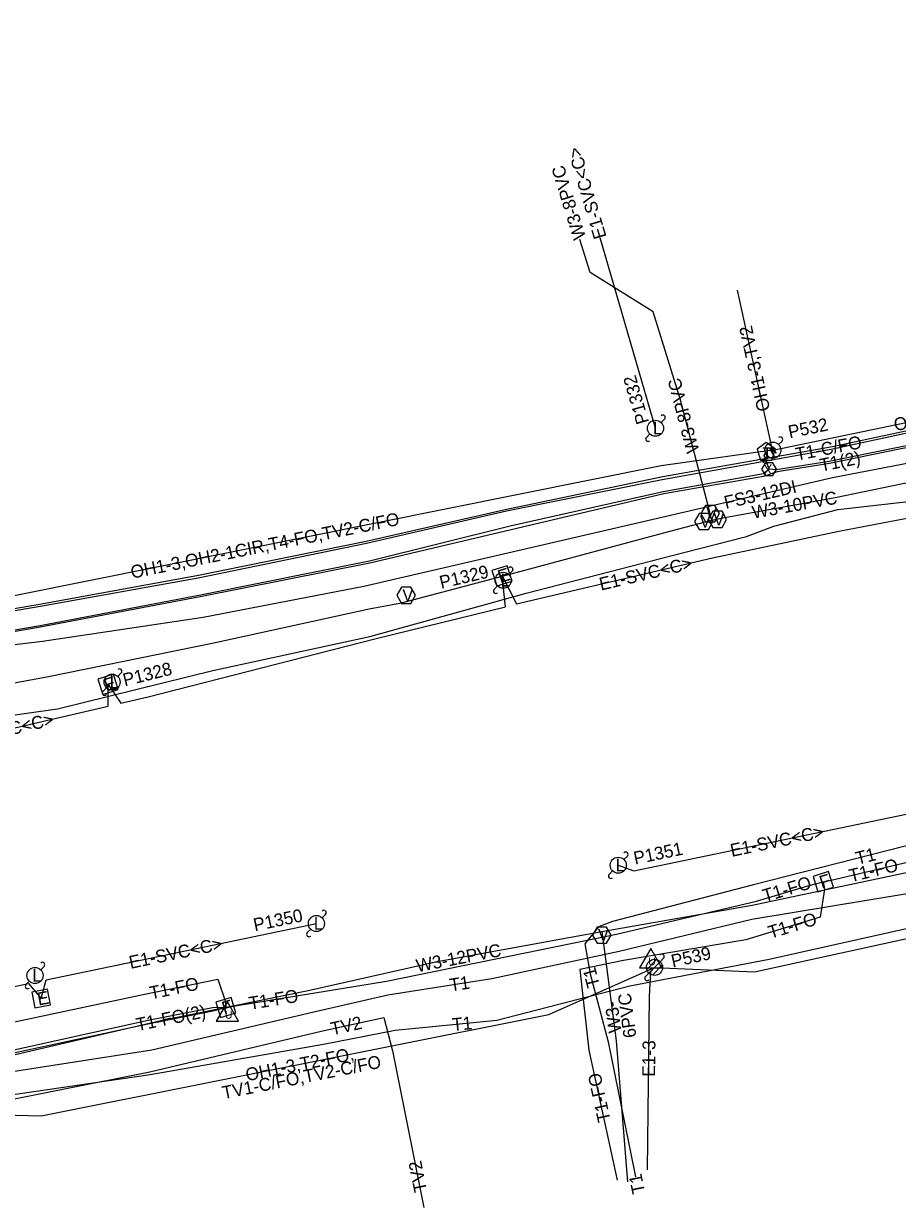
# Model space of a CAD drawing. Extents: x 2336688 to 2352634, y 362473 to 369571.
# Drawn here: x 2347488.6 to 2347760, y 367293.4 to 367661.1 of the extents above; entities that cross this region are included whole.
import ezdxf

# ---------------------------------------------------------------- set-up
doc = ezdxf.new("R2010")
doc.units = 0
for name, color, linetype in [('RD_EX_DV_Prop', 7, 'Continuous'), ('RD_EX_DV_TX_Prop', 7, 'Continuous'), ('RD_EX_RW', 7, 'Continuous'), ('RD_EX_RW_TX', 7, 'Continuous'), ('RD_HC_Data_Tic', 7, 'Continuous'), ('RD_PD_CstnLmt', 7, 'Continuous'), ('RD_PD_Final_TrvlWay', 7, 'Continuous'), ('RD_PD_PatLn3', 7, 'Continuous'), ('RD_PD_PatLn4', 7, 'Continuous'), ('RD_SHT_ShtClip', 7, 'Continuous'), ('RD_Sketch1', 7, 'Continuous'), ('RD_Sketch2', 7, 'Continuous'), ('RD_Sketch5', 7, 'Continuous')]:
    doc.layers.add(name, color=color, linetype=linetype)

msp = doc.modelspace()

# ---------------------------------------------------------------- linework, layer by layer
at = {"layer": 'RD_EX_RW_TX'}
for points in [[(2347470.44, 367444.23), (2347499.15, 367448.23), (2347547.38, 367460.16), (2347596.2, 367470.73), (2347644.67, 367484.24), (2347693.24, 367496.74), (2347713.15, 367501.75), (2347721.65, 367505), (2347741.52, 367510.17), (2347791.62, 367515.85), (2347841.03, 367525.03), (2347889.66, 367537.7), (2347924.48, 367550.59), (2347930.04, 367554.24), (2347932.17, 367555.74), (2347934, 367561.09), (2347931.82, 367574.4), (2347929.65, 367586.41), (2347915.95, 367650.55), (2347902.14, 367697.01)], [(2348277.67, 367644.22), (2348273.84, 367645.8), (2348227.29, 367635.33), (2348178.6, 367623.03), (2348133.33, 367611.87), (2348080.21, 367600.2), (2348034.92, 367588.57), (2348009.29, 367585.15), (2347982.98, 367580.09), (2347935.21, 367568.08), (2347896.24, 367563.27), (2347883.18, 367561.78), (2347837.9, 367550.42), (2347785.45, 367539.42), (2347739.83, 367529.65), (2347687.13, 367520.3), (2347638.22, 367510.11), (2347594.98, 367500.2), (2347542.99, 367489.7), (2347493.07, 367480.59), (2347455.62, 367474.3)], [(2348273.75, 367646.44), (2348227.32, 367635.79), (2348178.43, 367623.86), (2348133.17, 367612.62), (2348080.1, 367600.69), (2348034.75, 367588.91), (2347982.83, 367580.63), (2347949.32, 367569.72), (2347947.83, 367569.22), (2347941.99, 367566.16), (2347925.16, 367563.38), (2347893.98, 367560.65), (2347889.37, 367561.99), (2347883.21, 367561.02), (2347838.01, 367549.55), (2347785.59, 367538.72), (2347739.47, 367528.78), (2347686.93, 367519.36), (2347638.55, 367509.72), (2347595.16, 367499.67), (2347542.86, 367488.84), (2347493.21, 367479.93), (2347455.71, 367473.66)], [(2348277.67, 367644.22), (2348273.99, 367643.66), (2348228.58, 367631.8), (2348180.44, 367618.2), (2348135.72, 367603.5), (2348082.46, 367593.52), (2348035.48, 367584.74), (2347984.84, 367574.01), (2347951.44, 367567.02), (2347939.95, 367565.03), (2347935.77, 367564.67), (2347885.73, 367554.51), (2347837.63, 367544.73), (2347786.79, 367534.85), (2347738.82, 367525.14), (2347722.47, 367522.46), (2347720.16, 367522.7), (2347718.41, 367521.27), (2347687.23, 367515.7), (2347639.77, 367505.05), (2347596.04, 367494.09), (2347543.53, 367483.61), (2347493.77, 367474.07), (2347444.64, 367465.68)], [(2348277.67, 367644.22), (2348274.19, 367643.16), (2348263.65, 367639.56), (2348260.75, 367638.41), (2348228.6, 367631.4), (2348180.48, 367617.57), (2348135.89, 367603.05), (2348082.6, 367592.95), (2348035.55, 367584.09), (2347984.98, 367573.4), (2347951.16, 367566.33), (2347935.9, 367564.13), (2347885.75, 367553.87), (2347837.61, 367543.77), (2347786.94, 367534.28), (2347738.95, 367524.48), (2347722.65, 367521.86), (2347718.4, 367520.47), (2347687.46, 367515.07), (2347596.2, 367493.52), (2347543.48, 367483.07), (2347493.75, 367473.66), (2347444.81, 367465.06)], [(2347720.16, 367522.7), (2347718.58, 367527), (2347719.26, 367527.98)], [(2347470.17, 367338.02), (2347527.74, 367350.46), (2347547.36, 367354.41), (2347551.42, 367355.46), (2347554.94, 367356.11), (2347601.32, 367363.67), (2347672.79, 367378.26), (2347716.22, 367388.49), (2347732.21, 367393.25), (2347737, 367394.55), (2347740.32, 367395.23), (2347763.96, 367400.82), (2347812.85, 367411.94), (2347861.88, 367418.78), (2347886.02, 367419.64), (2347912.08, 367422.89), (2347964.53, 367437), (2348014.8, 367447.66), (2348042.92, 367455.01), (2348073.57, 367461.89), (2348119.92, 367473.29), (2348155.43, 367480.43), (2348206.38, 367490.17), (2348251.79, 367501.21)], [(2347762.8, 367405.7), (2347714.95, 367393.51), (2347671.52, 367382.16), (2347667.2, 367380.52), (2347662.95, 367375.22), (2347664.63, 367365.92), (2347670.14, 367344.81), (2347678.66, 367302.9)], [(2347737, 367394.55), (2347737.39, 367392.18), (2347736.03, 367383.58), (2347712.91, 367376.53), (2347674.98, 367370.11), (2347661.36, 367367.28), (2347664.2, 367342.23), (2347672.96, 367301.87)], [(2347471.76, 367333.48), (2347528.47, 367342.27), (2347578.72, 367354.1), (2347601.79, 367359.4), (2347634.08, 367364.43), (2347673.56, 367372.98), (2347714.77, 367382.86), (2347763.63, 367391.02)], [(2347473.23, 367326.64), (2347527.97, 367334.66), (2347581.75, 367344.07), (2347604.03, 367348.39), (2347635.63, 367351.49), (2347676.92, 367362.19), (2347720.23, 367370.45), (2347766.06, 367380.72)], [(2347468.18, 367347.3), (2347525.21, 367359.4), (2347548.99, 367364.25), (2347551.29, 367357.19), (2347551.42, 367355.46)], [(2347551.42, 367355.46), (2347547.27, 367355.37), (2347527.34, 367351.4), (2347470.01, 367338.79)], [(2347455.53, 367322.31), (2347459.94, 367322.89), (2347473.65, 367324.69), (2347527.79, 367335.44), (2347581.01, 367348.1), (2347600.51, 367352.4), (2347603.18, 367342.01), (2347612.97, 367293.38)]]:
    msp.add_lwpolyline(points, dxfattribs=at)
for points in [[(2347719.26, 367530.98), (2347716.41, 367528.91), (2347717.5, 367525.56), (2347721.02, 367525.56), (2347722.11, 367528.91)], [(2347717.85, 367522.7), (2347719.01, 367520.7), (2347721.32, 367520.7), (2347722.47, 367522.7), (2347721.32, 367524.7), (2347719.01, 367524.7)], [(2347738.66, 367397.67), (2347733.88, 367396.21), (2347735.34, 367391.43), (2347740.12, 367392.89)], [(2347553.08, 367358.58), (2347548.3, 367357.13), (2347549.76, 367352.34), (2347554.54, 367353.8)]]:
    msp.add_lwpolyline(points, close=True, dxfattribs=at)
at = {"layer": 'RD_HC_Data_Tic'}
for p, q in [((2347686.64, 367537.19), (2347687.7, 367538.25)), ((2347682.04, 367532.6), (2347683.1, 367533.66)), ((2347724.17, 367531.46), (2347723.1, 367530.4)), ((2347719.57, 367526.87), (2347718.51, 367525.81)), ((2347639.34, 367489.97), (2347640.4, 367491.03)), ((2347634.74, 367485.37), (2347635.8, 367486.43)), ((2347517.88, 367458.33), (2347518.94, 367459.39)), ((2347513.28, 367453.73), (2347514.35, 367454.79)), ((2347675.08, 367401.43), (2347676.14, 367402.49)), ((2347670.48, 367396.83), (2347671.54, 367397.89)), ((2347581.32, 367383.31), (2347582.38, 367384.38)), ((2347576.73, 367378.72), (2347577.79, 367379.78)), ((2347685.21, 367370.34), (2347682.15, 367367.28)), ((2347686.33, 367369.7), (2347682.8, 367366.16)), ((2347687.39, 367370.76), (2347686.33, 367369.7)), ((2347493.93, 367367.17), (2347494.99, 367368.23)), ((2347682.8, 367366.16), (2347681.74, 367365.1)), ((2347686.98, 367368.58), (2347683.92, 367365.51)), ((2347489.34, 367362.57), (2347490.4, 367363.63))]:
    msp.add_line(p, q, dxfattribs=at)
msp.add_lwpolyline([(2347721.73, 367526.62), (2347720.9, 367528.64), (2347722.36, 367527.84), (2347720.49, 367530.52), (2347720.49, 367530.52), (2347721.69, 367528.42), (2347720.31, 367529.22)], close=True, dxfattribs=at)
for centre in [(2347684.87, 367535.42), (2347721.34, 367528.63), (2347637.57, 367488.2), (2347516.11, 367456.56), (2347673.31, 367399.66), (2347579.56, 367381.55), (2347684.57, 367367.93), (2347492.17, 367365.4)]:
    msp.add_circle(centre, 2.5, dxfattribs=at)
for centre, start, end in [((2347687.17, 367538.78), 315, 135), ((2347682.57, 367532.07), 135, 315), ((2347723.64, 367531.99), 315, 135), ((2347719.04, 367525.28), 135, 315), ((2347639.87, 367491.56), 315, 135), ((2347635.27, 367484.84), 135, 315), ((2347518.41, 367459.92), 315, 135), ((2347513.81, 367453.2), 135, 315), ((2347675.61, 367403.02), 315, 135), ((2347671.01, 367396.3), 135, 315), ((2347581.85, 367384.91), 315, 135), ((2347577.26, 367378.19), 135, 315), ((2347494.46, 367368.76), 315, 135), ((2347686.86, 367371.29), 315, 135), ((2347682.27, 367364.57), 135, 315), ((2347489.87, 367362.04), 135, 315)]:
    msp.add_arc(centre, 0.75, start, end, dxfattribs=at)
at = {"layer": 'RD_PD_Final_TrvlWay'}
msp.add_line((2347684.87, 367535.42), (2347667.74, 367594.63), dxfattribs=at)
for points in [[(2347411.66, 367432.11), (2347416.41, 367427.52), (2347456.82, 367435.65), (2347514.93, 367449.13), (2347514.86, 367455.85), (2347518.86, 367450.04), (2347527.31, 367452), (2347598.1, 367470.08), (2347638.25, 367479.98), (2347637.21, 367489.58), (2347641.7, 367480.84), (2347702.59, 367495.22), (2347742.38, 367503.56), (2347770.63, 367508.97), (2347781.57, 367511.28), (2347780.95, 367520.78), (2347786.97, 367511.95), (2347822.4, 367519.43), (2347860.67, 367526.84), (2347915.43, 367542.21), (2347917.26, 367549.2)], [(2347673.31, 367399.66), (2347678.14, 367397.96), (2347796.1, 367422.52), (2347799.13, 367419.97), (2347801.17, 367423.58), (2347934.37, 367451.31), (2347934.6, 367451.36), (2347939.01, 367454.97), (2347937.23, 367432.36), (2347932.97, 367422.33)], [(2347294.89, 367322.22), (2347392.4, 367342.51), (2347396.75, 367338.07), (2347397.64, 367343.6), (2347451.77, 367354.89), (2347457.75, 367326.25), (2347458.2, 367322.79), (2347459.12, 367326.53), (2347453.14, 367355.18), (2347490.16, 367362.9), (2347494.09, 367358.25), (2347495.64, 367364.04), (2347579.56, 367381.55)], [(2347682.41, 367305.07), (2347683.02, 367358.86), (2347683.46, 367366.64), (2347684.57, 367367.93)]]:
    msp.add_lwpolyline(points, dxfattribs=at)
for points in [[(2347638.84, 367492.71), (2347634.07, 367491.21), (2347635.58, 367486.44), (2347640.34, 367487.95)], [(2347516.49, 367458.98), (2347511.72, 367457.48), (2347513.23, 367452.71), (2347517.99, 367454.22)], [(2347496.09, 367361.17), (2347491.17, 367360.24), (2347492.1, 367355.33), (2347497.01, 367356.25)]]:
    msp.add_lwpolyline(points, close=True, dxfattribs=at)
at = {"layer": 'RD_PD_PatLn3'}
for points in [[(2347683.39, 367373.77), (2347679.92, 367367.77), (2347686.85, 367367.77)], [(2347551.93, 367357.21), (2347548.47, 367351.21), (2347555.39, 367351.21)]]:
    msp.add_lwpolyline(points, close=True, dxfattribs=at)
at = {"layer": 'RD_SHT_ShtClip'}
for p, q in [((2347721.34, 367528.63), (2348013.81, 367589.41)), ((2347721.24, 367528.57), (2347710.34, 367578.37))]:
    msp.add_line(p, q, dxfattribs=at)
for points in [[(2347721.24, 367528.57), (2347686.62, 367523.73), (2347442.35, 367474.67), (2347408.44, 367465.79)], [(2347684.57, 367367.93), (2347715.59, 367366.51), (2347905.38, 367408.07), (2347932.97, 367422.33)], [(2347458.2, 367322.79), (2347494.08, 367321.83), (2347651.8, 367353.28), (2347684.57, 367367.93)]]:
    msp.add_lwpolyline(points, dxfattribs=at)
at = {"layer": 'RD_Sketch2'}
for points in [[(2347449.95, 367449.7), (2347496.38, 367458.28), (2347547.67, 367468.78), (2347595.96, 367479.29), (2347606, 367481.2), (2347641.64, 367490.61), (2347690.17, 367503.64), (2347702.37, 367506.83), (2347705.77, 367507.63), (2347740.68, 367513.89), (2347788.69, 367523.87), (2347838.62, 367531.94), (2347879.94, 367537.81), (2347883.63, 367538.5), (2347938.54, 367549.3), (2348009.43, 367561.67), (2348086.12, 367578.47), (2348135.82, 367588.03), (2348185.16, 367600.49), (2348233.5, 367612.99), (2348282.05, 367625.96)], [(2347702.34, 367506.82), (2347701.86, 367508.9), (2347701.43, 367510.62), (2347692.54, 367544.57), (2347684.12, 367571.63), (2347664.55, 367583.83), (2347661.41, 367594.1)], [(2347470.35, 367337.23), (2347531.2, 367351.47), (2347577.01, 367360.75), (2347616.5, 367369.7), (2347668.2, 367379.09), (2347714.88, 367387.21), (2347764.3, 367397.77), (2347812.02, 367409.64), (2347861.32, 367422.45), (2347913.79, 367430.89), (2347937.03, 367433), (2347933.07, 367452.68), (2347964.62, 367460.29), (2348009.08, 367466.62), (2348042.26, 367474.52), (2348049.97, 367475.89), (2348057.53, 367476.89), (2348069.08, 367477.92), (2348103, 367487.1), (2348151.7, 367499.89), (2348204.32, 367511.65), (2348252.13, 367524.59)], [(2347668.2, 367379.09), (2347669, 367372.87), (2347672.68, 367345.06), (2347676.14, 367301.35)]]:
    msp.add_lwpolyline(points, dxfattribs=at)
for points in [[(2347702.73, 367506.46), (2347701.29, 367508.95), (2347698.4, 367508.95), (2347696.96, 367506.46), (2347698.4, 367503.96), (2347701.29, 367503.96)], [(2347704.74, 367508.9), (2347703.3, 367511.4), (2347700.41, 367511.4), (2347698.97, 367508.9), (2347700.41, 367506.4), (2347703.3, 367506.4)], [(2347706.98, 367507.13), (2347705.54, 367509.63), (2347702.65, 367509.63), (2347701.21, 367507.13), (2347702.65, 367504.63), (2347705.54, 367504.63)], [(2347610.36, 367483.53), (2347608.92, 367486.03), (2347606.03, 367486.03), (2347604.59, 367483.53), (2347606.03, 367481.03), (2347608.92, 367481.03)], [(2347671.12, 367377.95), (2347669.68, 367380.44), (2347666.79, 367380.44), (2347665.35, 367377.95), (2347666.79, 367375.45), (2347669.68, 367375.45)]]:
    msp.add_lwpolyline(points, close=True, dxfattribs=at)
at = {"layer": 'RD_Sketch5'}
msp.add_lwpolyline([(2347445.27, 367463.42), (2347494.44, 367469.25), (2347544.4, 367476.73), (2347594.33, 367486.36), (2347688.22, 367508.14), (2347739.9, 367520.09), (2347788.33, 367529.45), (2347838.31, 367540.64), (2347886.7, 367551.33), (2347928.19, 367559.84), (2347952.54, 367563.69), (2347985.72, 367570.62), (2348036.5, 367580.92), (2348083.37, 367589.22), (2348136.57, 367600.6), (2348182.34, 367611.84), (2348232.74, 367624.03), (2348279.47, 367637.63), (2348326.25, 367651.54), (2348374.55, 367665.64), (2348421.71, 367681.15), (2348468.93, 367697.05), (2348491.54, 367705.13)], dxfattribs=at)

# ---------------------------------------------------------------- texts
at = {"layer": 'RD_EX_DV_Prop'}
for s, rotation, p in [('E1-SVC<C>', 106.4202, (2347669.71, 367594.92)), ('E1-SVC<C>', 13.2952, (2347667.94, 367484.98)), ('E1-SVC<C>', 13.0568, (2347469.6, 367436.56)), ('E1-SVC<C>', 11.7605, (2347708.56, 367402.25)), ('E1-SVC<C>', 11.7823, (2347521.82, 367367.46)), ('E1-3', 89.3439, (2347684.74, 367333.95))]:
    msp.add_text(s, height=4, rotation=rotation, dxfattribs=at).set_placement(p)
at = {"layer": 'RD_EX_DV_TX_Prop'}
for s, rotation, p in [('P1332', 106.1378, (2347682.93, 367537.36)), ('P532', 11.7386, (2347726.54, 367532.25)), ('P1329', 13.2952, (2347618.32, 367485.54)), ('P1328', 14.0384, (2347520.02, 367455.21)), ('P1351', 11.7539, (2347678.53, 367399.84)), ('P1350', 11.7539, (2347560.44, 367379.11)), ('P539', 12.353, (2347690.22, 367367.87))]:
    msp.add_text(s, height=4, rotation=rotation, dxfattribs=at).set_placement(p)
at = {"layer": 'RD_EX_RW'}
for s, rotation, p in [('T1-C/FO', 10.9327, (2347728.77, 367525.33)), ('T1(2)', 11.541, (2347736.34, 367521.91)), ('T1', 14.2968, (2347747.61, 367399.77)), ('T1-FO', 13.3144, (2347745.51, 367394.37)), ('T1-FO', 16.5838, (2347718.82, 367388.14)), ('T1-FO', 16.9649, (2347720.58, 367376.78)), ('T1', 8.8544, (2347621.25, 367360.4)), ('T1', 104.6293, (2347667.66, 367362.25)), ('T1-FO', 11.5224, (2347528.18, 367357.97)), ('T1-FO', 9.2531, (2347558.93, 367354.74)), ('T1-FO(2)', 11.3801, (2347523.98, 367348.12)), ('TV2', 12.4379, (2347584.46, 367346.81)), ('T1', 5.6041, (2347621.91, 367348.13)), ('T1-FO', 102.2408, (2347671, 367320.33)), ('TV2', 101.3912, (2347613.98, 367298.52)), ('T1', 101.4849, (2347681.7, 367298))]:
    msp.add_text(s, height=4, rotation=rotation, dxfattribs=at).set_placement(p)
at = {"layer": 'RD_EX_RW_TX'}
msp.add_text('T', height=3.75, dxfattribs=at).set_placement((2347718.03, 367525.76))
for s, height, rotation, p in [('X', 3, 180, (2347721.11, 367524.2)), ('F', 4, 16.9682, (2347736.5, 367392.31)), ('F', 4, 16.9682, (2347550.92, 367353.22))]:
    msp.add_text(s, height=height, rotation=rotation, dxfattribs=at).set_placement(p)
at = {"layer": 'RD_HC_Data_Tic'}
for p in [(2347684.06, 367533.49), (2347636.76, 367486.26), (2347515.3, 367454.63), (2347672.5, 367397.73), (2347578.74, 367379.61), (2347491.35, 367363.47)]:
    msp.add_text('L', height=4, rotation=360, dxfattribs=at).set_placement(p)
at = {"layer": 'RD_PD_CstnLmt'}
for s, rotation, p in [('W3-8PVC', 107.0101, (2347663.31, 367594.72)), ('W3-8PVC', 104.6659, (2347698.53, 367528.34)), ('W3-10PVC', 10.1703, (2347715.27, 367507.3)), ('W3-12PVC', 10.8553, (2347610.96, 367366.41)), ('6PVC', 97.5456, (2347678.97, 367346.31)), ('W3-', 97.5456, (2347674.33, 367347.84))]:
    msp.add_text(s, height=4, rotation=rotation, dxfattribs=at).set_placement(p)
at = {"layer": 'RD_PD_Final_TrvlWay'}
for rotation, p in [(17.5359, (2347636.65, 367487.31)), (17.5359, (2347514.3, 367453.57)), (10.6261, (2347493.27, 367356.06))]:
    msp.add_text('E', height=4, rotation=rotation, dxfattribs=at).set_placement(p)
at = {"layer": 'RD_PD_PatLn3'}
for p in [(2347682.63, 367368.57), (2347551.17, 367352.01)]:
    msp.add_text('U', height=2.4, dxfattribs=at).set_placement(p)
at = {"layer": 'RD_PD_PatLn4'}
for s, rotation, p in [('OH1-3,TV2', 102.3446, (2347720.53, 367541.16)), ('OH1-3,OH2-1CIR,T4-FO', 11.7386, (2347759.36, 367534.49)), ('OH1-3,OH2-1CIR,T4-FO,TV2-C/FO', 11.3573, (2347522.31, 367488.69)), ('TV1-C/FO,TV2-C/FO', 11.2785, (2347550.69, 367326.96)), ('OH1-3,T2-FO,', 11.2785, (2347558.01, 367332.54))]:
    msp.add_text(s, height=4, rotation=rotation, dxfattribs=at).set_placement(p)
at = {"layer": 'RD_Sketch1'}
msp.add_text('FS3-12DI', height=4, rotation=13.021, dxfattribs=at).set_placement((2347706.7, 367510.36))
at = {"layer": 'RD_Sketch2'}
for p in [(2347700.65, 367507.03), (2347702.88, 367505.26), (2347698.64, 367504.58), (2347606.27, 367481.66), (2347667.03, 367376.07)]:
    msp.add_text('V', height=3.75, dxfattribs=at).set_placement(p)

doc.saveas('drawing.dxf')
